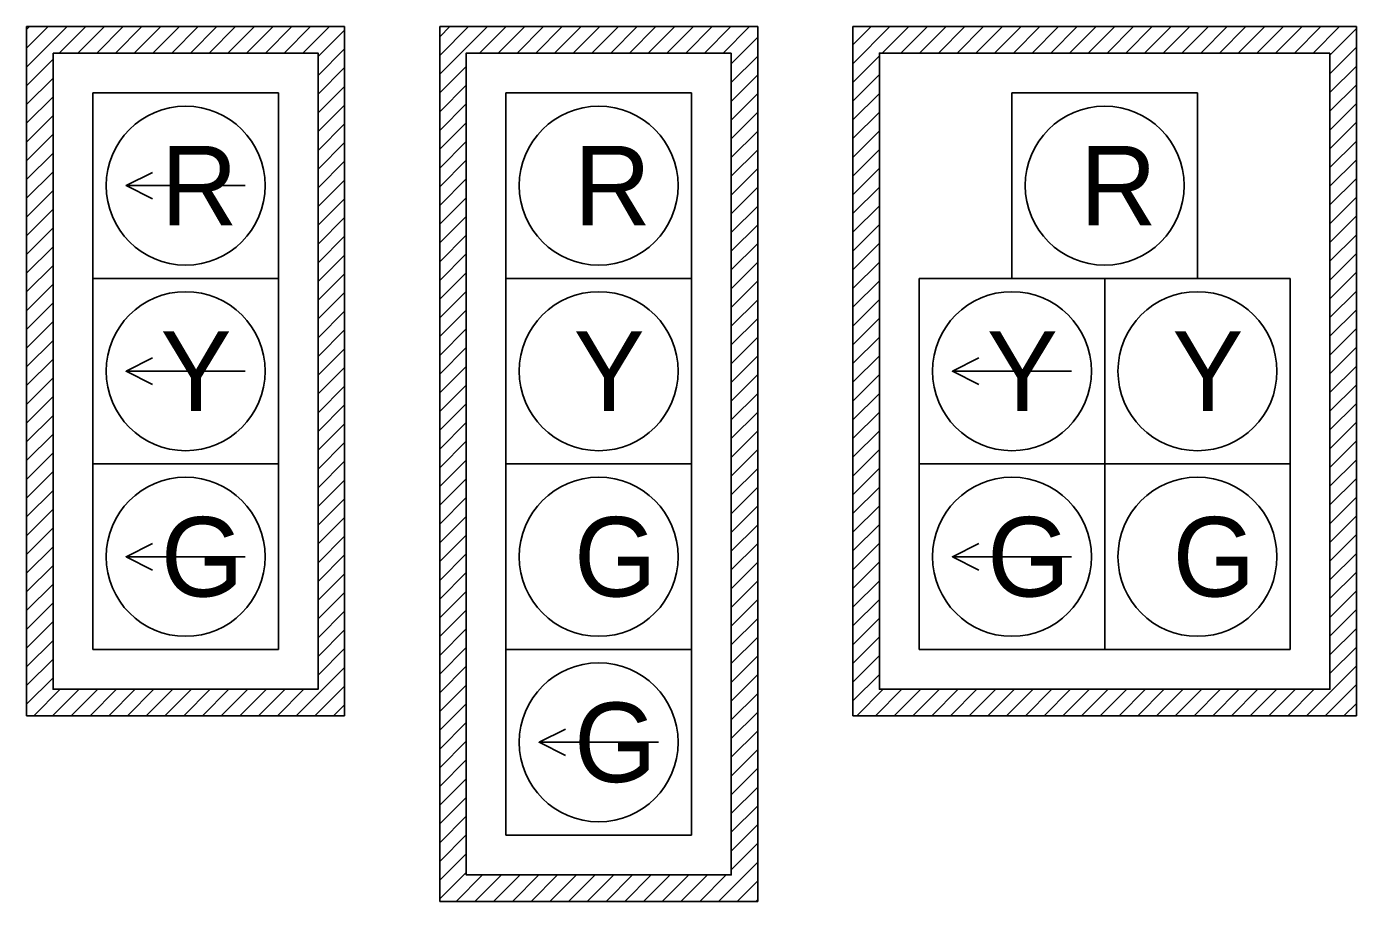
# Model space of a CAD drawing. Extents: x 1736833 to 1738623, y 544707 to 545544.
# Drawn here: x 1737069.9 to 1737170.3, y 545255.6 to 545321.6 of the extents above; entities that cross this region are included whole.
import ezdxf

# ---------------------------------------------------------------- set-up
doc = ezdxf.new("R2010")
doc.units = 0
doc.layers.add('T_Drafting', color=7, linetype='Continuous')

msp = doc.modelspace()

# ---------------------------------------------------------------- linework, layer by layer
at = {"layer": 'T_Drafting'}
for p, q in [((1737069.9, 545321.61), (1737093.9, 545321.61)), ((1737069.9, 545269.61), (1737069.9, 545321.61)), ((1737069.9, 545318.56), (1737072.95, 545321.61)), ((1737069.9, 545319.97), (1737071.53, 545321.61)), ((1737069.9, 545321.39), (1737070.12, 545321.61)), ((1737072.36, 545319.61), (1737074.36, 545321.61)), ((1737073.77, 545319.61), (1737075.77, 545321.61)), ((1737075.19, 545319.61), (1737077.19, 545321.61)), ((1737076.6, 545319.61), (1737078.6, 545321.61)), ((1737078.02, 545319.61), (1737080.02, 545321.61)), ((1737079.43, 545319.61), (1737081.43, 545321.61)), ((1737080.85, 545319.61), (1737082.85, 545321.61)), ((1737082.26, 545319.61), (1737084.26, 545321.61)), ((1737083.67, 545319.61), (1737085.67, 545321.61)), ((1737085.09, 545319.61), (1737087.09, 545321.61)), ((1737086.5, 545319.61), (1737088.5, 545321.61)), ((1737087.92, 545319.61), (1737089.92, 545321.61)), ((1737089.33, 545319.61), (1737091.33, 545321.61)), ((1737090.75, 545319.61), (1737092.75, 545321.61)), ((1737093.9, 545321.61), (1737093.9, 545269.61)), ((1737125.08, 545321.61), (1737101.08, 545321.61)), ((1737101.08, 545321.61), (1737101.08, 545255.61)), ((1737101.08, 545318.02), (1737104.68, 545321.61)), ((1737101.08, 545319.43), (1737103.26, 545321.61)), ((1737101.08, 545320.84), (1737101.85, 545321.61)), ((1737104.09, 545319.61), (1737106.09, 545321.61)), ((1737105.5, 545319.61), (1737107.5, 545321.61)), ((1737106.92, 545319.61), (1737108.92, 545321.61)), ((1737108.33, 545319.61), (1737110.33, 545321.61)), ((1737109.75, 545319.61), (1737111.75, 545321.61)), ((1737111.16, 545319.61), (1737113.16, 545321.61)), ((1737112.57, 545319.61), (1737114.57, 545321.61)), ((1737113.99, 545319.61), (1737115.99, 545321.61)), ((1737115.4, 545319.61), (1737117.4, 545321.61)), ((1737116.82, 545319.61), (1737118.82, 545321.61)), ((1737118.23, 545319.61), (1737120.23, 545321.61)), ((1737119.65, 545319.61), (1737121.65, 545321.61)), ((1737121.06, 545319.61), (1737123.06, 545321.61)), ((1737122.47, 545319.61), (1737124.47, 545321.61)), ((1737125.08, 545255.61), (1737125.08, 545321.61)), ((1737170.27, 545321.61), (1737132.27, 545321.61)), ((1737132.27, 545321.61), (1737132.27, 545269.61)), ((1737132.27, 545318.81), (1737135.06, 545321.61)), ((1737132.27, 545320.23), (1737133.65, 545321.61)), ((1737134.48, 545319.61), (1737136.48, 545321.61)), ((1737135.89, 545319.61), (1737137.89, 545321.61)), ((1737137.3, 545319.61), (1737139.3, 545321.61)), ((1737138.72, 545319.61), (1737140.72, 545321.61)), ((1737140.13, 545319.61), (1737142.13, 545321.61)), ((1737141.55, 545319.61), (1737143.55, 545321.61)), ((1737142.96, 545319.61), (1737144.96, 545321.61)), ((1737144.38, 545319.61), (1737146.38, 545321.61)), ((1737145.79, 545319.61), (1737147.79, 545321.61)), ((1737147.2, 545319.61), (1737149.2, 545321.61)), ((1737148.62, 545319.61), (1737150.62, 545321.61)), ((1737150.03, 545319.61), (1737152.03, 545321.61)), ((1737151.45, 545319.61), (1737153.45, 545321.61)), ((1737152.86, 545319.61), (1737154.86, 545321.61)), ((1737154.28, 545319.61), (1737156.28, 545321.61)), ((1737155.69, 545319.61), (1737157.69, 545321.61)), ((1737157.1, 545319.61), (1737159.1, 545321.61)), ((1737158.52, 545319.61), (1737160.52, 545321.61)), ((1737159.93, 545319.61), (1737161.93, 545321.61)), ((1737161.35, 545319.61), (1737163.35, 545321.61)), ((1737162.76, 545319.61), (1737164.76, 545321.61)), ((1737164.17, 545319.61), (1737166.17, 545321.61)), ((1737165.59, 545319.61), (1737167.59, 545321.61)), ((1737167, 545319.61), (1737169, 545321.61)), ((1737170.27, 545269.61), (1737170.27, 545321.61)), ((1737091.9, 545319.35), (1737093.9, 545321.35)), ((1737123.08, 545318.8), (1737125.08, 545320.8)), ((1737168.27, 545319.46), (1737170.27, 545321.46)), ((1737091.9, 545317.93), (1737093.9, 545319.93)), ((1737168.27, 545318.05), (1737170.27, 545320.05)), ((1737069.9, 545317.14), (1737071.9, 545319.14)), ((1737101.08, 545316.6), (1737103.08, 545318.6)), ((1737123.08, 545317.39), (1737125.08, 545319.39)), ((1737132.27, 545317.4), (1737134.27, 545319.4)), ((1737168.27, 545316.63), (1737170.27, 545318.63)), ((1737069.9, 545315.73), (1737071.9, 545317.73)), ((1737091.9, 545316.52), (1737093.9, 545318.52)), ((1737123.08, 545315.97), (1737125.08, 545317.97)), ((1737132.27, 545315.99), (1737134.27, 545317.99)), ((1737074.9, 545316.61), (1737088.9, 545316.61)), ((1737074.9, 545316.61), (1737074.9, 545302.61)), ((1737088.9, 545316.61), (1737088.9, 545302.61)), ((1737091.9, 545315.1), (1737093.9, 545317.1)), ((1737101.08, 545315.19), (1737103.08, 545317.19)), ((1737106.08, 545316.61), (1737120.08, 545316.61)), ((1737106.08, 545316.61), (1737106.08, 545302.61)), ((1737120.08, 545316.61), (1737120.08, 545302.61)), ((1737123.08, 545314.56), (1737125.08, 545316.56)), ((1737132.27, 545314.57), (1737134.27, 545316.57)), ((1737144.27, 545316.61), (1737158.27, 545316.61)), ((1737144.27, 545316.61), (1737144.27, 545302.61)), ((1737158.27, 545316.61), (1737158.27, 545302.61)), ((1737168.27, 545315.22), (1737170.27, 545317.22)), ((1737069.9, 545314.32), (1737071.9, 545316.32)), ((1737091.9, 545313.69), (1737093.9, 545315.69)), ((1737101.08, 545313.77), (1737103.08, 545315.77)), ((1737168.27, 545313.8), (1737170.27, 545315.8)), ((1737069.9, 545312.9), (1737071.9, 545314.9)), ((1737123.08, 545313.15), (1737125.08, 545315.15)), ((1737132.27, 545313.16), (1737134.27, 545315.16)), ((1737091.9, 545312.27), (1737093.9, 545314.27)), ((1737101.08, 545312.36), (1737103.08, 545314.36)), ((1737123.08, 545311.73), (1737125.08, 545313.73)), ((1737132.27, 545311.74), (1737134.27, 545313.74)), ((1737168.27, 545312.39), (1737170.27, 545314.39)), ((1737069.9, 545311.49), (1737071.9, 545313.49)), ((1737091.9, 545310.86), (1737093.9, 545312.86)), ((1737101.08, 545310.94), (1737103.08, 545312.94)), ((1737168.27, 545310.97), (1737170.27, 545312.97)), ((1737069.9, 545310.07), (1737071.9, 545312.07)), ((1737101.08, 545309.53), (1737103.08, 545311.53)), ((1737123.08, 545310.32), (1737125.08, 545312.32)), ((1737132.27, 545310.33), (1737134.27, 545312.33)), ((1737168.27, 545309.56), (1737170.27, 545311.56)), ((1737069.9, 545308.66), (1737071.9, 545310.66)), ((1737091.9, 545309.45), (1737093.9, 545311.45)), ((1737123.08, 545308.9), (1737125.08, 545310.9)), ((1737132.27, 545308.92), (1737134.27, 545310.92)), ((1737086.4, 545309.61), (1737077.4, 545309.61)), ((1737091.9, 545308.03), (1737093.9, 545310.03)), ((1737101.08, 545308.12), (1737103.08, 545310.12)), ((1737168.27, 545308.15), (1737170.27, 545310.15)), ((1737069.9, 545307.24), (1737071.9, 545309.24)), ((1737091.9, 545306.62), (1737093.9, 545308.62)), ((1737101.08, 545306.7), (1737103.08, 545308.7)), ((1737123.08, 545307.49), (1737125.08, 545309.49)), ((1737132.27, 545307.5), (1737134.27, 545309.5)), ((1737168.27, 545306.73), (1737170.27, 545308.73)), ((1737069.9, 545305.83), (1737071.9, 545307.83)), ((1737123.08, 545306.07), (1737125.08, 545308.07)), ((1737132.27, 545306.09), (1737134.27, 545308.09)), ((1737091.9, 545305.2), (1737093.9, 545307.2)), ((1737101.08, 545305.29), (1737103.08, 545307.29)), ((1737123.08, 545304.66), (1737125.08, 545306.66)), ((1737132.27, 545304.67), (1737134.27, 545306.67)), ((1737168.27, 545305.32), (1737170.27, 545307.32)), ((1737069.9, 545304.42), (1737071.9, 545306.42)), ((1737091.9, 545303.79), (1737093.9, 545305.79)), ((1737101.08, 545303.87), (1737103.08, 545305.87)), ((1737168.27, 545303.9), (1737170.27, 545305.9)), ((1737069.9, 545303), (1737071.9, 545305)), ((1737123.08, 545303.25), (1737125.08, 545305.25)), ((1737132.27, 545303.26), (1737134.27, 545305.26)), ((1737069.9, 545301.59), (1737071.9, 545303.59)), ((1737091.9, 545302.37), (1737093.9, 545304.37)), ((1737101.08, 545302.46), (1737103.08, 545304.46)), ((1737123.08, 545301.83), (1737125.08, 545303.83)), ((1737132.27, 545301.84), (1737134.27, 545303.84)), ((1737168.27, 545302.49), (1737170.27, 545304.49)), ((1737074.9, 545302.61), (1737088.9, 545302.61)), ((1737074.9, 545302.61), (1737074.9, 545288.61)), ((1737088.9, 545302.61), (1737088.9, 545288.61)), ((1737091.9, 545300.96), (1737093.9, 545302.96)), ((1737101.08, 545301.04), (1737103.08, 545303.04)), ((1737106.08, 545302.61), (1737120.08, 545302.61)), ((1737106.08, 545302.61), (1737106.08, 545288.61)), ((1737120.08, 545302.61), (1737120.08, 545288.61)), ((1737137.27, 545302.61), (1737137.27, 545288.61)), ((1737137.27, 545302.61), (1737151.27, 545302.61)), ((1737151.27, 545302.61), (1737151.27, 545288.61)), ((1737151.27, 545302.61), (1737165.27, 545302.61)), ((1737151.27, 545302.61), (1737151.27, 545288.61)), ((1737165.27, 545302.61), (1737165.27, 545288.61)), ((1737168.27, 545301.07), (1737170.27, 545303.07)), ((1737069.9, 545300.17), (1737071.9, 545302.17)), ((1737091.9, 545299.55), (1737093.9, 545301.55)), ((1737101.08, 545299.63), (1737103.08, 545301.63)), ((1737123.08, 545300.42), (1737125.08, 545302.42)), ((1737132.27, 545300.43), (1737134.27, 545302.43)), ((1737168.27, 545299.66), (1737170.27, 545301.66)), ((1737069.9, 545298.76), (1737071.9, 545300.76)), ((1737123.08, 545299), (1737125.08, 545301)), ((1737132.27, 545299.02), (1737134.27, 545301.02)), ((1737091.9, 545298.13), (1737093.9, 545300.13)), ((1737101.08, 545298.22), (1737103.08, 545300.22)), ((1737123.08, 545297.59), (1737125.08, 545299.59)), ((1737132.27, 545297.6), (1737134.27, 545299.6)), ((1737168.27, 545298.25), (1737170.27, 545300.25)), ((1737069.9, 545297.35), (1737071.9, 545299.35)), ((1737091.9, 545296.72), (1737093.9, 545298.72)), ((1737101.08, 545296.8), (1737103.08, 545298.8)), ((1737168.27, 545296.83), (1737170.27, 545298.83)), ((1737069.9, 545295.93), (1737071.9, 545297.93)), ((1737123.08, 545296.17), (1737125.08, 545298.17)), ((1737132.27, 545296.19), (1737134.27, 545298.19)), ((1737069.9, 545294.52), (1737071.9, 545296.52)), ((1737091.9, 545295.3), (1737093.9, 545297.3)), ((1737101.08, 545295.39), (1737103.08, 545297.39)), ((1737123.08, 545294.76), (1737125.08, 545296.76)), ((1737132.27, 545294.77), (1737134.27, 545296.77)), ((1737168.27, 545295.42), (1737170.27, 545297.42)), ((1737086.4, 545295.61), (1737077.4, 545295.61)), ((1737091.9, 545293.89), (1737093.9, 545295.89)), ((1737101.08, 545293.97), (1737103.08, 545295.97)), ((1737148.77, 545295.61), (1737139.77, 545295.61)), ((1737168.27, 545294), (1737170.27, 545296)), ((1737069.9, 545293.1), (1737071.9, 545295.1)), ((1737091.9, 545292.48), (1737093.9, 545294.48)), ((1737101.08, 545292.56), (1737103.08, 545294.56)), ((1737123.08, 545293.35), (1737125.08, 545295.35)), ((1737132.27, 545293.36), (1737134.27, 545295.36)), ((1737168.27, 545292.59), (1737170.27, 545294.59)), ((1737069.9, 545291.69), (1737071.9, 545293.69)), ((1737123.08, 545291.93), (1737125.08, 545293.93)), ((1737132.27, 545291.94), (1737134.27, 545293.94)), ((1737091.9, 545291.06), (1737093.9, 545293.06)), ((1737101.08, 545291.15), (1737103.08, 545293.15)), ((1737123.08, 545290.52), (1737125.08, 545292.52)), ((1737132.27, 545290.53), (1737134.27, 545292.53)), ((1737168.27, 545291.18), (1737170.27, 545293.18)), ((1737069.9, 545290.27), (1737071.9, 545292.27)), ((1737091.9, 545289.65), (1737093.9, 545291.65)), ((1737101.08, 545289.73), (1737103.08, 545291.73)), ((1737168.27, 545289.76), (1737170.27, 545291.76)), ((1737069.9, 545288.86), (1737071.9, 545290.86)), ((1737123.08, 545289.1), (1737125.08, 545291.1)), ((1737132.27, 545289.12), (1737134.27, 545291.12)), ((1737069.9, 545287.45), (1737071.9, 545289.45)), ((1737091.9, 545288.23), (1737093.9, 545290.23)), ((1737101.08, 545288.32), (1737103.08, 545290.32)), ((1737123.08, 545287.69), (1737125.08, 545289.69)), ((1737132.27, 545287.7), (1737134.27, 545289.7)), ((1737168.27, 545288.35), (1737170.27, 545290.35)), ((1737074.9, 545288.61), (1737088.9, 545288.61)), ((1737074.9, 545288.61), (1737074.9, 545274.61)), ((1737088.9, 545288.61), (1737088.9, 545274.61)), ((1737091.9, 545286.82), (1737093.9, 545288.82)), ((1737101.08, 545286.9), (1737103.08, 545288.9)), ((1737106.08, 545288.61), (1737120.08, 545288.61)), ((1737106.08, 545288.61), (1737106.08, 545274.61)), ((1737120.08, 545288.61), (1737120.08, 545274.61)), ((1737137.27, 545288.61), (1737151.27, 545288.61)), ((1737137.27, 545288.61), (1737137.27, 545274.61)), ((1737151.27, 545288.61), (1737151.27, 545274.61)), ((1737151.27, 545288.61), (1737165.27, 545288.61)), ((1737151.27, 545288.61), (1737151.27, 545274.61)), ((1737165.27, 545288.61), (1737165.27, 545274.61)), ((1737168.27, 545286.93), (1737170.27, 545288.93)), ((1737069.9, 545286.03), (1737071.9, 545288.03)), ((1737101.08, 545285.49), (1737103.08, 545287.49)), ((1737123.08, 545286.28), (1737125.08, 545288.28)), ((1737132.27, 545286.29), (1737134.27, 545288.29)), ((1737168.27, 545285.52), (1737170.27, 545287.52)), ((1737069.9, 545284.62), (1737071.9, 545286.62)), ((1737091.9, 545285.4), (1737093.9, 545287.4)), ((1737123.08, 545284.86), (1737125.08, 545286.86)), ((1737132.27, 545284.87), (1737134.27, 545286.87)), ((1737091.9, 545283.99), (1737093.9, 545285.99)), ((1737101.08, 545284.07), (1737103.08, 545286.07)), ((1737123.08, 545283.45), (1737125.08, 545285.45)), ((1737132.27, 545283.46), (1737134.27, 545285.46)), ((1737168.27, 545284.1), (1737170.27, 545286.1)), ((1737069.9, 545283.2), (1737071.9, 545285.2)), ((1737091.9, 545282.58), (1737093.9, 545284.58)), ((1737101.08, 545282.66), (1737103.08, 545284.66)), ((1737168.27, 545282.69), (1737170.27, 545284.69)), ((1737069.9, 545281.79), (1737071.9, 545283.79)), ((1737123.08, 545282.03), (1737125.08, 545284.03)), ((1737132.27, 545282.05), (1737134.27, 545284.05)), ((1737091.9, 545281.16), (1737093.9, 545283.16)), ((1737101.08, 545281.25), (1737103.08, 545283.25)), ((1737123.08, 545280.62), (1737125.08, 545282.62)), ((1737132.27, 545280.63), (1737134.27, 545282.63)), ((1737168.27, 545281.28), (1737170.27, 545283.28)), ((1737069.9, 545280.37), (1737071.9, 545282.37)), ((1737086.4, 545281.61), (1737077.4, 545281.61)), ((1737091.9, 545279.75), (1737093.9, 545281.75)), ((1737101.08, 545279.83), (1737103.08, 545281.83)), ((1737148.77, 545281.61), (1737139.77, 545281.61)), ((1737168.27, 545279.86), (1737170.27, 545281.86)), ((1737069.9, 545278.96), (1737071.9, 545280.96)), ((1737101.08, 545278.42), (1737103.08, 545280.42)), ((1737123.08, 545279.2), (1737125.08, 545281.2)), ((1737132.27, 545279.22), (1737134.27, 545281.22)), ((1737168.27, 545278.45), (1737170.27, 545280.45)), ((1737069.9, 545277.55), (1737071.9, 545279.55)), ((1737091.9, 545278.33), (1737093.9, 545280.33)), ((1737123.08, 545277.79), (1737125.08, 545279.79)), ((1737132.27, 545277.8), (1737134.27, 545279.8)), ((1737091.9, 545276.92), (1737093.9, 545278.92)), ((1737101.08, 545277), (1737103.08, 545279)), ((1737168.27, 545277.03), (1737170.27, 545279.03)), ((1737069.9, 545276.13), (1737071.9, 545278.13)), ((1737091.9, 545275.5), (1737093.9, 545277.5)), ((1737101.08, 545275.59), (1737103.08, 545277.59)), ((1737123.08, 545276.38), (1737125.08, 545278.38)), ((1737132.27, 545276.39), (1737134.27, 545278.39)), ((1737168.27, 545275.62), (1737170.27, 545277.62)), ((1737069.9, 545274.72), (1737071.9, 545276.72)), ((1737123.08, 545274.96), (1737125.08, 545276.96)), ((1737132.27, 545274.97), (1737134.27, 545276.97)), ((1737091.9, 545274.09), (1737093.9, 545276.09)), ((1737101.08, 545274.17), (1737103.08, 545276.17)), ((1737123.08, 545273.55), (1737125.08, 545275.55)), ((1737132.27, 545273.56), (1737134.27, 545275.56)), ((1737168.27, 545274.2), (1737170.27, 545276.2)), ((1737069.9, 545273.3), (1737071.9, 545275.3)), ((1737074.9, 545274.61), (1737088.9, 545274.61)), ((1737091.9, 545272.68), (1737093.9, 545274.68)), ((1737101.08, 545272.76), (1737103.08, 545274.76)), ((1737106.08, 545274.61), (1737120.08, 545274.61)), ((1737106.08, 545274.61), (1737106.08, 545260.61)), ((1737120.08, 545274.61), (1737120.08, 545260.61)), ((1737137.27, 545274.61), (1737151.27, 545274.61)), ((1737151.27, 545274.61), (1737165.27, 545274.61)), ((1737168.27, 545272.79), (1737170.27, 545274.79)), ((1737069.9, 545271.89), (1737071.9, 545273.89)), ((1737123.08, 545272.13), (1737125.08, 545274.13)), ((1737132.27, 545272.15), (1737134.27, 545274.15)), ((1737069.9, 545270.48), (1737071.9, 545272.48)), ((1737090.24, 545269.61), (1737093.9, 545273.26)), ((1737101.08, 545271.35), (1737103.08, 545273.35)), ((1737123.08, 545270.72), (1737125.08, 545272.72)), ((1737132.27, 545270.73), (1737134.27, 545272.73)), ((1737166.5, 545269.61), (1737170.27, 545273.38)), ((1737070.44, 545269.61), (1737072.44, 545271.61)), ((1737071.86, 545269.61), (1737073.86, 545271.61)), ((1737073.27, 545269.61), (1737075.27, 545271.61)), ((1737074.69, 545269.61), (1737076.69, 545271.61)), ((1737076.1, 545269.61), (1737078.1, 545271.61)), ((1737077.51, 545269.61), (1737079.51, 545271.61)), ((1737078.93, 545269.61), (1737080.93, 545271.61)), ((1737080.34, 545269.61), (1737082.34, 545271.61)), ((1737081.76, 545269.61), (1737083.76, 545271.61)), ((1737083.17, 545269.61), (1737085.17, 545271.61)), ((1737084.59, 545269.61), (1737086.59, 545271.61)), ((1737086, 545269.61), (1737088, 545271.61)), ((1737087.41, 545269.61), (1737089.41, 545271.61)), ((1737088.83, 545269.61), (1737090.83, 545271.61)), ((1737091.66, 545269.61), (1737093.9, 545271.85)), ((1737101.08, 545269.93), (1737103.08, 545271.93)), ((1737132.56, 545269.61), (1737134.56, 545271.61)), ((1737133.97, 545269.61), (1737135.97, 545271.61)), ((1737135.39, 545269.61), (1737137.39, 545271.61)), ((1737136.8, 545269.61), (1737138.8, 545271.61)), ((1737138.22, 545269.61), (1737140.22, 545271.61)), ((1737139.63, 545269.61), (1737141.63, 545271.61)), ((1737141.05, 545269.61), (1737143.05, 545271.61)), ((1737142.46, 545269.61), (1737144.46, 545271.61)), ((1737143.87, 545269.61), (1737145.87, 545271.61)), ((1737145.29, 545269.61), (1737147.29, 545271.61)), ((1737146.7, 545269.61), (1737148.7, 545271.61)), ((1737148.12, 545269.61), (1737150.12, 545271.61)), ((1737149.53, 545269.61), (1737151.53, 545271.61)), ((1737150.94, 545269.61), (1737152.94, 545271.61)), ((1737152.36, 545269.61), (1737154.36, 545271.61)), ((1737153.77, 545269.61), (1737155.77, 545271.61)), ((1737155.19, 545269.61), (1737157.19, 545271.61)), ((1737156.6, 545269.61), (1737158.6, 545271.61)), ((1737158.02, 545269.61), (1737160.02, 545271.61)), ((1737159.43, 545269.61), (1737161.43, 545271.61)), ((1737160.84, 545269.61), (1737162.84, 545271.61)), ((1737162.26, 545269.61), (1737164.26, 545271.61)), ((1737163.67, 545269.61), (1737165.67, 545271.61)), ((1737165.09, 545269.61), (1737167.09, 545271.61)), ((1737167.92, 545269.61), (1737170.27, 545271.96)), ((1737093.07, 545269.61), (1737093.9, 545270.43)), ((1737101.08, 545268.52), (1737103.08, 545270.52)), ((1737123.08, 545269.3), (1737125.08, 545271.3)), ((1737169.33, 545269.61), (1737170.27, 545270.55)), ((1737093.9, 545269.61), (1737069.9, 545269.61)), ((1737123.08, 545267.89), (1737125.08, 545269.89)), ((1737132.27, 545269.61), (1737170.27, 545269.61)), ((1737101.08, 545267.1), (1737103.08, 545269.1)), ((1737123.08, 545266.48), (1737125.08, 545268.48)), ((1737101.08, 545265.69), (1737103.08, 545267.69)), ((1737117.58, 545267.61), (1737108.58, 545267.61)), ((1737123.08, 545265.06), (1737125.08, 545267.06)), ((1737101.08, 545264.28), (1737103.08, 545266.28)), ((1737123.08, 545263.65), (1737125.08, 545265.65)), ((1737101.08, 545262.86), (1737103.08, 545264.86)), ((1737101.08, 545261.45), (1737103.08, 545263.45)), ((1737123.08, 545262.23), (1737125.08, 545264.23)), ((1737123.08, 545260.82), (1737125.08, 545262.82)), ((1737101.08, 545260.03), (1737103.08, 545262.03)), ((1737123.08, 545259.41), (1737125.08, 545261.41)), ((1737101.08, 545258.62), (1737103.08, 545260.62)), ((1737106.08, 545260.61), (1737120.08, 545260.61)), ((1737123.08, 545257.99), (1737125.08, 545259.99)), ((1737101.08, 545257.2), (1737103.08, 545259.2)), ((1737122.11, 545255.61), (1737125.08, 545258.58)), ((1737101.08, 545255.79), (1737103.08, 545257.79)), ((1737102.32, 545255.61), (1737104.32, 545257.61)), ((1737103.73, 545255.61), (1737105.73, 545257.61)), ((1737105.14, 545255.61), (1737107.14, 545257.61)), ((1737106.56, 545255.61), (1737108.56, 545257.61)), ((1737107.97, 545255.61), (1737109.97, 545257.61)), ((1737109.39, 545255.61), (1737111.39, 545257.61)), ((1737110.8, 545255.61), (1737112.8, 545257.61)), ((1737112.21, 545255.61), (1737114.21, 545257.61)), ((1737113.63, 545255.61), (1737115.63, 545257.61)), ((1737115.04, 545255.61), (1737117.04, 545257.61)), ((1737116.46, 545255.61), (1737118.46, 545257.61)), ((1737117.87, 545255.61), (1737119.87, 545257.61)), ((1737119.29, 545255.61), (1737121.29, 545257.61)), ((1737120.7, 545255.61), (1737122.7, 545257.61)), ((1737123.53, 545255.61), (1737125.08, 545257.16)), ((1737101.08, 545255.61), (1737125.08, 545255.61)), ((1737124.94, 545255.61), (1737125.08, 545255.75))]:
    msp.add_line(p, q, dxfattribs=at)
for points in [[(1737071.9, 545319.61), (1737091.9, 545319.61), (1737091.9, 545271.61), (1737071.9, 545271.61)], [(1737123.08, 545319.61), (1737103.08, 545319.61), (1737103.08, 545257.61), (1737123.08, 545257.61)], [(1737168.27, 545319.61), (1737134.27, 545319.61), (1737134.27, 545271.61), (1737168.27, 545271.61)]]:
    msp.add_lwpolyline(points, close=True, dxfattribs=at)
for points in [[(1737079.4, 545310.61), (1737077.4, 545309.61), (1737079.4, 545308.61)], [(1737079.4, 545296.61), (1737077.4, 545295.61), (1737079.4, 545294.61)], [(1737141.77, 545296.61), (1737139.77, 545295.61), (1737141.77, 545294.61)], [(1737079.4, 545282.61), (1737077.4, 545281.61), (1737079.4, 545280.61)], [(1737141.77, 545282.61), (1737139.77, 545281.61), (1737141.77, 545280.61)], [(1737110.58, 545268.61), (1737108.58, 545267.61), (1737110.58, 545266.61)]]:
    msp.add_lwpolyline(points, dxfattribs=at)
for centre in [(1737081.9, 545309.61), (1737113.08, 545309.61), (1737151.27, 545309.61), (1737081.9, 545295.61), (1737113.08, 545295.61), (1737144.27, 545295.61), (1737158.27, 545295.61), (1737081.9, 545281.61), (1737113.08, 545281.61), (1737144.27, 545281.61), (1737158.27, 545281.61), (1737113.08, 545267.61)]:
    msp.add_circle(centre, 6, dxfattribs=at)

# ---------------------------------------------------------------- texts
for s, p in [('R', (1737080.03, 545306.61)), ('R', (1737111.22, 545306.61)), ('R', (1737149.4, 545306.61)), ('Y', (1737080.01, 545292.61)), ('Y', (1737111.19, 545292.61)), ('Y', (1737142.38, 545292.61)), ('Y', (1737156.38, 545292.61)), ('G', (1737080.03, 545278.61)), ('G', (1737111.22, 545278.61)), ('G', (1737142.4, 545278.61)), ('G', (1737156.4, 545278.61)), ('G', (1737111.22, 545264.61))]:
    msp.add_text(s, height=6, dxfattribs=at).set_placement(p)

doc.saveas('drawing.dxf')
